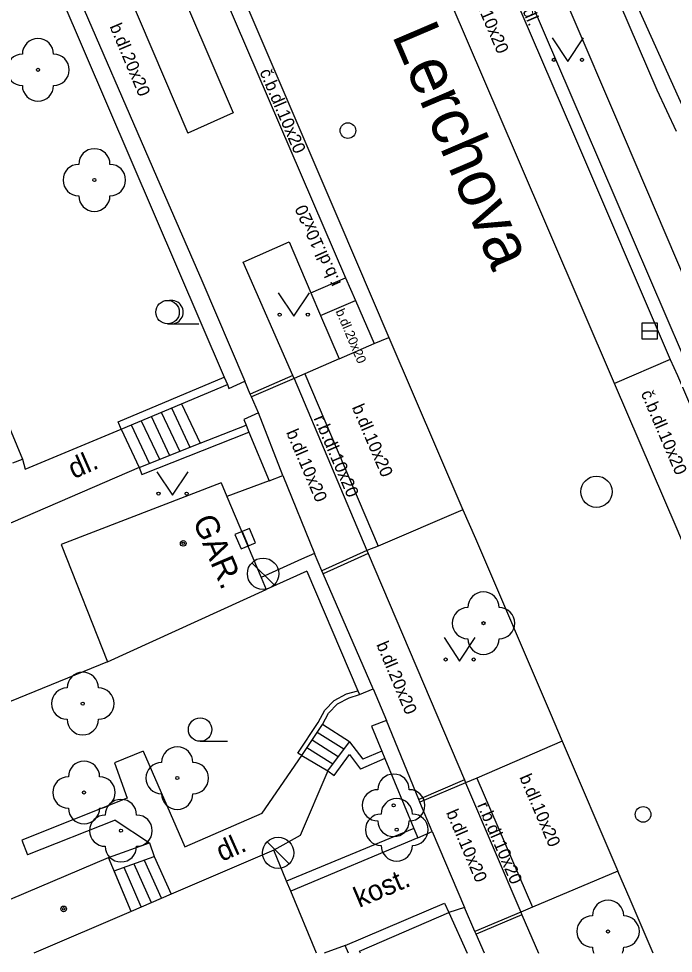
# Model space of a CAD drawing. Extents: x -600391 to -599491, y -1160176 to -1159402.
# Drawn here: x -599902.02 to -599881.11, y -1160176.08 to -1160146.21 of the extents above; entities that cross this region are included whole.
import ezdxf

# ---------------------------------------------------------------- set-up
doc = ezdxf.new("R2010")
doc.units = 0
for name, color, linetype in [('Level 10', 7, 'Continuous'), ('Level 11', 7, 'Continuous'), ('Level 22', 7, 'Continuous'), ('Level 27', 7, 'Continuous'), ('Level 28', 7, 'Continuous'), ('Level 36', 7, 'Continuous'), ('Level 39', 7, 'Continuous'), ('Level 40', 7, 'Continuous'), ('Level 41', 7, 'Continuous'), ('Level 5', 7, 'Continuous'), ('Level 50', 7, 'Continuous'), ('Level 6', 7, 'Continuous'), ('Level 7', 7, 'Continuous'), ('Level 8', 7, 'Continuous')]:
    doc.layers.add(name, color=color, linetype=linetype)

msp = doc.modelspace()

# ---------------------------------------------------------------- linework, layer by layer
at = {"layer": 'Level 10'}
for points in [[(-599900.25, -1160112.71), (-599895.14, -1160124.63), (-599894.96, -1160125.07), (-599894.75, -1160125.54), (-599893.06, -1160129.49), (-599892.08, -1160131.73), (-599890.71, -1160134.94), (-599890.53, -1160135.39), (-599884.33, -1160149.82), (-599881.2, -1160157.1), (-599880.97, -1160157.62), (-599879.19, -1160161.76), (-599879.01, -1160162.2)], [(-599903.64, -1160125.12), (-599901.38, -1160130.37), (-599899.78, -1160134.07), (-599895.66, -1160143.63), (-599891.79, -1160152.66), (-599890.19, -1160156.4), (-599887.83, -1160161.91), (-599887.42, -1160162.82), (-599885.04, -1160168.39), (-599884.65, -1160169.3), (-599882.88, -1160173.45)], [(-599881.745, -1160176.079), (-599882.48, -1160174.36), (-599882.88, -1160173.45)]]:
    msp.add_lwpolyline(points, dxfattribs=at)
at = {"layer": 'Level 11'}
msp.add_line((-599891.59, -1160175.83), (-599892.253, -1160176.079), dxfattribs=at)
for points in [[(-599880.3, -1160164.15), (-599880.98, -1160162.53), (-599882.98, -1160157.87), (-599886.11, -1160150.57), (-599892.31, -1160136.14), (-599894.43, -1160131.2), (-599896.75, -1160125.82), (-599902.04, -1160113.48), (-599906.68, -1160102.7), (-599908.55, -1160098.32), (-599910.62, -1160093.45), (-599915.66, -1160081.71)], [(-599889.36, -1160134.37), (-599889.32, -1160134.46), (-599882.98, -1160149.28), (-599879.7, -1160156.97), (-599879.66, -1160157.06)], [(-599880.57, -1160157.46), (-599880.81, -1160156.93), (-599883.94, -1160149.65), (-599890.33, -1160134.78)], [(-599902.82, -1160135.35), (-599902.78, -1160135.44), (-599896.61, -1160149.87)], [(-599896.16, -1160143.84), (-599891.58, -1160154.5), (-599891.26, -1160155.22), (-599890.66, -1160156.59)], [(-599897.27, -1160144.3), (-599895.16, -1160149.22), (-599896.61, -1160149.87)], [(-599894.85, -1160153.99), (-599893.38, -1160153.34), (-599892.68, -1160154.97), (-599892.37, -1160155.7), (-599891.78, -1160157.08)], [(-599893.22, -1160157.71), (-599893.26, -1160157.62), (-599894.85, -1160153.99)], [(-599892.68, -1160154.97), (-599891.58, -1160154.5)], [(-599892.37, -1160155.7), (-599891.26, -1160155.22)], [(-599891.78, -1160157.08), (-599890.66, -1160156.59), (-599890.19, -1160156.4)], [(-599891.78, -1160157.08), (-599892.88, -1160157.56)], [(-599881.2, -1160157.1), (-599882.98, -1160157.87)], [(-599893.26, -1160157.62), (-599894.62, -1160158.21)], [(-599892.88, -1160157.56), (-599893.22, -1160157.71)], [(-599892.88, -1160157.56), (-599890.53, -1160163.07)], [(-599893.22, -1160157.71), (-599894.58, -1160158.3)], [(-599893.22, -1160157.71), (-599890.89, -1160163.21)], [(-599896.82, -1160158.52), (-599896.22, -1160159.78)], [(-599897.46, -1160158.79), (-599896.87, -1160160.04)], [(-599897.14, -1160158.65), (-599896.55, -1160159.91)], [(-599898.42, -1160159.19), (-599897.85, -1160160.42)], [(-599898.1, -1160159.06), (-599897.52, -1160160.29)], [(-599897.78, -1160158.92), (-599897.2, -1160160.17)], [(-599901.81, -1160160.61), (-599898.74, -1160159.33)], [(-599898.74, -1160159.33), (-599898.17, -1160160.55)], [(-599901.9, -1160160.29), (-599901.81, -1160160.61)], [(-599898.17, -1160160.55), (-599902.6, -1160162.47)], [(-599894.01, -1160160.98), (-599895.37, -1160161.48)], [(-599887.83, -1160161.91), (-599890.53, -1160163.07)], [(-599890.53, -1160163.07), (-599890.89, -1160163.21)], [(-599890.89, -1160163.21), (-599892.33, -1160163.86)], [(-599890.85, -1160163.3), (-599892.29, -1160163.95)], [(-599890.89, -1160163.21), (-599890.85, -1160163.3), (-599887.78, -1160170.54), (-599887.74, -1160170.63)], [(-599891.63, -1160169.56), (-599892.48, -1160169.02)], [(-599891.45, -1160169.32), (-599892.31, -1160168.77)], [(-599891.81, -1160169.8), (-599892.64, -1160169.27)], [(-599884.65, -1160169.3), (-599887.38, -1160170.48), (-599887.74, -1160170.63)], [(-599898.04, -1160169.62), (-599898.96, -1160169.99)], [(-599898.04, -1160169.62), (-599896.71, -1160172.68)], [(-599891.98, -1160170.04), (-599892.81, -1160169.51)], [(-599894.24, -1160171.6), (-599892.97, -1160169.76)], [(-599892.97, -1160169.76), (-599892.14, -1160170.25)], [(-599898.96, -1160169.99), (-599898.55, -1160171.12)], [(-599892.14, -1160170.25), (-599893.03, -1160172.31)], [(-599887.78, -1160170.54), (-599889.23, -1160171.16)], [(-599887.38, -1160170.48), (-599885.6, -1160174.6)], [(-599887.74, -1160170.63), (-599889.2, -1160171.25)], [(-599887.74, -1160170.63), (-599885.98, -1160174.76)], [(-599898.55, -1160171.12), (-599901.92, -1160172.46)], [(-599896.71, -1160172.68), (-599894.24, -1160171.6)], [(-599898.94, -1160171.82), (-599901.73, -1160172.93)], [(-599898.94, -1160171.82), (-599897.84, -1160172.55)], [(-599893.03, -1160172.31), (-599893.87, -1160172.78)], [(-599901.92, -1160172.46), (-599901.73, -1160172.93)], [(-599898.34, -1160173.22), (-599897.79, -1160174.45)], [(-599898.01, -1160173.1), (-599897.47, -1160174.31)], [(-599897.69, -1160172.98), (-599897.15, -1160174.19)], [(-599898.66, -1160173.33), (-599898.11, -1160174.58)], [(-599882.88, -1160173.45), (-599885.6, -1160174.6), (-599885.98, -1160174.76)], [(-599885.98, -1160174.76), (-599887.44, -1160175.38)], [(-599885.94, -1160174.85), (-599887.4, -1160175.47)], [(-599885.98, -1160174.76), (-599885.94, -1160174.85), (-599885.415, -1160176.079)]]:
    msp.add_lwpolyline(points, dxfattribs=at)
at = {"layer": 'Level 22'}
for centre in [(-599901.4, -1160147.85), (-599899.6, -1160151.37), (-599887.17, -1160165.53), (-599899.97, -1160168.1), (-599896.95, -1160170.48), (-599899.93, -1160170.94), (-599890.04, -1160171.35), (-599898.75, -1160172.16), (-599889.94, -1160172.13), (-599883.19, -1160175.38)]:
    msp.add_circle(centre, 0.05, dxfattribs=at)
for centre, start, end in [((-599901.4, -1160147.35), 0, 180), ((-599901.9, -1160147.85), 90, 270), ((-599900.9, -1160147.85), 270, 90), ((-599901.4, -1160148.35), 180, 0), ((-599899.6, -1160150.87), 0, 180), ((-599900.1, -1160151.37), 90, 270), ((-599899.1, -1160151.37), 270, 90), ((-599899.6, -1160151.87), 180, 0), ((-599887.17, -1160165.03), 0, 180), ((-599887.67, -1160165.53), 90, 270), ((-599886.67, -1160165.53), 270, 90), ((-599887.17, -1160166.03), 180, 0), ((-599899.97, -1160167.6), 0, 180), ((-599900.47, -1160168.1), 90, 270), ((-599899.47, -1160168.1), 270, 90), ((-599899.97, -1160168.6), 180, 0), ((-599896.95, -1160169.98), 0, 180), ((-599899.93, -1160170.44), 0, 180), ((-599897.45, -1160170.48), 90, 270), ((-599896.45, -1160170.48), 270, 90), ((-599900.43, -1160170.94), 90, 270), ((-599899.43, -1160170.94), 270, 90), ((-599890.04, -1160170.85), 0, 180), ((-599896.95, -1160170.98), 180, 0), ((-599890.54, -1160171.35), 90, 270), ((-599889.94, -1160171.63), 0, 180), ((-599889.54, -1160171.35), 270, 90), ((-599899.93, -1160171.44), 180, 0), ((-599898.75, -1160171.66), 0, 180), ((-599899.25, -1160172.16), 90, 270), ((-599898.25, -1160172.16), 270, 90), ((-599890.44, -1160172.13), 90, 270), ((-599889.44, -1160172.13), 270, 90), ((-599890.04, -1160171.85), 180, 0), ((-599889.94, -1160172.63), 180, 0), ((-599898.75, -1160172.66), 180, 0), ((-599883.19, -1160174.88), 0, 180), ((-599883.69, -1160175.38), 90, 270), ((-599882.69, -1160175.38), 270, 90), ((-599883.19, -1160175.88), 180, 203.4042), ((-599883.19, -1160175.88), 336.5958, 0)]:
    msp.add_arc(centre, 0.5, start, end, dxfattribs=at)
at = {"layer": 'Level 27'}
for p, q in [((-599882.11, -1160156.19), (-599881.61, -1160156.19)), ((-599894.878, -1160162.6), (-599894.682, -1160163.06)), ((-599893.857, -1160164.304), (-599894.564, -1160163.597)), ((-599893.377, -1160173.224), (-599894.084, -1160172.517))]:
    msp.add_line(p, q, dxfattribs=at)
for points in [[(-599882.11, -1160156.44), (-599881.61, -1160156.44), (-599881.61, -1160155.94), (-599882.11, -1160155.94)], [(-599895.108, -1160162.698), (-599894.912, -1160163.158), (-599894.452, -1160162.962), (-599894.648, -1160162.502)]]:
    msp.add_lwpolyline(points, close=True, dxfattribs=at)
for centre in [(-599883.56, -1160161.33), (-599894.21, -1160163.95), (-599893.73, -1160172.87)]:
    msp.add_circle(centre, 0.5, dxfattribs=at)
at = {"layer": 'Level 28'}
for centre in [(-599891.5, -1160149.79), (-599882.07, -1160171.64)]:
    msp.add_circle(centre, 0.25, dxfattribs=at)
at = {"layer": 'Level 36'}
for p, q in [((-599897.26, -1160155.965), (-599896.26, -1160155.965)), ((-599896.22, -1160169.305), (-599895.345, -1160169.305))]:
    msp.add_line(p, q, dxfattribs=at)
for points in [[(-599884.97, -1160146.83), (-599884.47, -1160147.58), (-599883.97, -1160146.83)], [(-599893.73, -1160154.97), (-599893.23, -1160155.72), (-599892.73, -1160154.97)], [(-599897.6, -1160160.69), (-599897.1, -1160161.44), (-599896.6, -1160160.69)], [(-599888.43, -1160165.99), (-599887.93, -1160166.74), (-599887.43, -1160165.99)]]:
    msp.add_lwpolyline(points, dxfattribs=at)
for centre, radius in [((-599884.92, -1160147.53), 0.05), ((-599884.021, -1160147.53), 0.05), ((-599897.26, -1160155.59), 0.375), ((-599893.68, -1160155.67), 0.05), ((-599892.781, -1160155.67), 0.05), ((-599897.55, -1160161.39), 0.05), ((-599896.651, -1160161.39), 0.05), ((-599888.38, -1160166.69), 0.05), ((-599887.481, -1160166.69), 0.05), ((-599896.22, -1160168.93), 0.375)]:
    msp.add_circle(centre, radius, dxfattribs=at)
msp.add_arc((-599897.135, -1160155.59), 0.375, 260.4059, 99.5941, dxfattribs=at)
at = {"layer": 'Level 39'}
for centre, radius in [((-599896.76, -1160162.98), 0.09), ((-599896.76, -1160162.98), 0.0398), ((-599900.58, -1160174.66), 0.09), ((-599900.58, -1160174.66), 0.0398)]:
    msp.add_circle(centre, radius, dxfattribs=at)
at = {"layer": 'Level 5'}
for points in [[(-599895.55, -1160161.04), (-599900.66, -1160163.02)], [(-599895.55, -1160161.04), (-599895.37, -1160161.48), (-599894.27, -1160164.07), (-599894.11, -1160164.45)], [(-599900.66, -1160163.02), (-599899.18, -1160166.76)], [(-599899.18, -1160166.76), (-599894.11, -1160164.45)], [(-599893.87, -1160172.78), (-599897.15, -1160174.19), (-599898.42, -1160174.74), (-599901.538, -1160176.079)], [(-599892.503, -1160176.079), (-599893.32, -1160174.09), (-599893.46, -1160173.77), (-599893.87, -1160172.78)], [(-599902.72, -1160174.53), (-599899.15, -1160173.02)], [(-599898.42, -1160174.74), (-599899.15, -1160173.02)], [(-599898.42, -1160174.74), (-599898.97, -1160173.44)]]:
    msp.add_lwpolyline(points, dxfattribs=at)
at = {"layer": 'Level 6'}
msp.add_line((-599892.503, -1160176.079), (-599893.32, -1160174.09), dxfattribs=at)
at = {"layer": 'Level 7'}
for points in [[(-599904.36, -1160135.72), (-599904.25, -1160135.96), (-599904.21, -1160136.06), (-599900.17, -1160145.36), (-599897.86, -1160150.69), (-599897.61, -1160151.26), (-599896.17, -1160154.58), (-599894.79, -1160157.8)], [(-599886.79, -1160136.46), (-599883.12, -1160145.01), (-599881.63, -1160148.49), (-599881.01, -1160149.81)], [(-599880.53, -1160149.62), (-599882.7, -1160144.81)], [(-599900.67, -1160145.51), (-599895.45, -1160157.67), (-599895.35, -1160157.9), (-599895.3, -1160158.03)], [(-599903.77, -1160155.79), (-599901.9, -1160160.29)], [(-599898.84, -1160159.1), (-599895.45, -1160157.67)], [(-599898.74, -1160159.33), (-599896.82, -1160158.52), (-599895.35, -1160157.9)], [(-599895.3, -1160158.03), (-599894.79, -1160157.8)], [(-599894.36, -1160158.81), (-599894.82, -1160159.02)], [(-599893.58, -1160160.81), (-599894.36, -1160158.81)], [(-599898.74, -1160159.33), (-599898.84, -1160159.1)], [(-599898.17, -1160160.55), (-599896.22, -1160159.78), (-599894.75, -1160159.2)], [(-599894.82, -1160159.02), (-599894.75, -1160159.2), (-599894.66, -1160159.43), (-599894.01, -1160160.98)], [(-599898.08, -1160160.78), (-599894.66, -1160159.43)], [(-599902.2, -1160160.41), (-599901.9, -1160160.29)], [(-599898.17, -1160160.55), (-599898.08, -1160160.78)], [(-599894.01, -1160160.98), (-599893.58, -1160160.81)], [(-599892.57, -1160163.3), (-599892.98, -1160163.48)], [(-599890.69, -1160167.63), (-599892.29, -1160163.95), (-599892.33, -1160163.86), (-599892.57, -1160163.3)], [(-599892.98, -1160163.48), (-599894.27, -1160164.07)], [(-599892.81, -1160163.87), (-599894.11, -1160164.45)], [(-599892.81, -1160163.87), (-599891.18, -1160167.69)], [(-599899.18, -1160166.76), (-599908.82, -1160170.7)], [(-599892.45, -1160168.7), (-599892.24, -1160168.31), (-599891.94, -1160168), (-599891.55, -1160167.79), (-599891.18, -1160167.69)], [(-599892.31, -1160168.77), (-599892.12, -1160168.4), (-599891.83, -1160168.11), (-599891.46, -1160167.92), (-599891.13, -1160167.81)], [(-599891.18, -1160167.69), (-599891.13, -1160167.81)], [(-599891.13, -1160167.81), (-599890.69, -1160167.63)], [(-599893.1, -1160169.68), (-599892.45, -1160168.7)], [(-599890.27, -1160168.64), (-599890.75, -1160168.82)], [(-599888.81, -1160172.19), (-599889.2, -1160171.25), (-599889.23, -1160171.16), (-599890.27, -1160168.64)], [(-599892.97, -1160169.76), (-599892.31, -1160168.77)], [(-599890.75, -1160168.82), (-599890.42, -1160169.62), (-599890.32, -1160169.85), (-599889.39, -1160172.09), (-599889.27, -1160172.39)], [(-599892.14, -1160170.25), (-599891.45, -1160169.32)], [(-599891.45, -1160169.32), (-599891.02, -1160169.88)], [(-599890.42, -1160169.62), (-599891.02, -1160169.88)], [(-599892.97, -1160169.76), (-599893.1, -1160169.68)], [(-599891.94, -1160170.4), (-599891.45, -1160169.73)], [(-599891.45, -1160169.73), (-599891.1, -1160170.19)], [(-599890.32, -1160169.85), (-599891.1, -1160170.19)], [(-599892.14, -1160170.25), (-599891.94, -1160170.4)], [(-599889.39, -1160172.09), (-599893.46, -1160173.77)], [(-599889.27, -1160172.39), (-599888.81, -1160172.19)], [(-599899.15, -1160173.02), (-599897.84, -1160172.55)], [(-599897.84, -1160172.55), (-599897.69, -1160172.98)], [(-599889.27, -1160172.39), (-599893.32, -1160174.09)], [(-599898.97, -1160173.44), (-599897.69, -1160172.98)], [(-599891.485, -1160176.079), (-599891.59, -1160175.83), (-599888.41, -1160174.48)], [(-599888.41, -1160174.48), (-599888.28, -1160174.77), (-599887.691, -1160176.079)], [(-599887.78, -1160174.61), (-599888.28, -1160174.77)], [(-599887.132, -1160176.079), (-599887.4, -1160175.47), (-599887.44, -1160175.38), (-599887.78, -1160174.61)], [(-599891.101, -1160176.079), (-599891.13, -1160176.01), (-599888.28, -1160174.77)]]:
    msp.add_lwpolyline(points, dxfattribs=at)
at = {"layer": 'Level 8'}
for points in [[(-599894.36, -1160158.81), (-599894.58, -1160158.3), (-599894.62, -1160158.21), (-599894.79, -1160157.8)], [(-599893.58, -1160160.81), (-599892.57, -1160163.3)], [(-599890.69, -1160167.63), (-599890.27, -1160168.64)], [(-599888.81, -1160172.19), (-599887.78, -1160174.61)]]:
    msp.add_lwpolyline(points, dxfattribs=at)

# ---------------------------------------------------------------- texts
at = {"layer": 'Level 40'}
for s, height, rotation, p in [('b.dl.10x20', 0.4, 293.1381, (-599887.68, -1160145.1)), ('zatr.dl.', 0.4, 293.3292, (-599886.34, -1160145.01)), ('b.dl.20x20', 0.4, 292.7805, (-599899.12, -1160146.46)), ('č.b.dl.10x20', 0.4, 293.1381, (-599894.33, -1160147.91)), ('r.b.dl.10x20', 0.39992, 114, (-599891.71, -1160154.67)), ('b.dl.20x20', 0.3, 293.0615, (-599891.9, -1160155.56)), ('č.b.dl.10x20', 0.4, 293.1381, (-599882.15, -1160158.18)), ('b.dl.10x20', 0.4, 293.1381, (-599891.38, -1160158.63)), ('r.b.dl.10x20', 0.39995, 293.1661, (-599892.6, -1160158.98)), ('b.dl.10x20', 0.4, 293.1381, (-599893.48, -1160159.43)), ('dl.', 0.65, 23.6029, (-599900.26, -1160160.93)), ('dl.', 0.65, 23.6029, (-599900.26, -1160160.93)), ('b.dl.20x20', 0.4, 292.7805, (-599890.6, -1160166.21)), ('b.dl.10x20', 0.4, 293.1381, (-599886.03, -1160170.45)), ('r.b.dl.10x20', 0.39995, 293.1661, (-599887.38, -1160171.34)), ('b.dl.10x20', 0.4, 293.1381, (-599888.37, -1160171.58)), ('dl.', 0.65, 24, (-599895.53, -1160173.16)), ('kost.', 0.65, 23.0569, (-599891.14, -1160174.63))]:
    msp.add_text(s, height=height, rotation=rotation, dxfattribs=at).set_placement(p)
at = {"layer": 'Level 41'}
msp.add_text('GAR.', height=0.75, rotation=293.042, dxfattribs=at).set_placement((-599896.47, -1160162.25))
at = {"layer": 'Level 50'}
msp.add_text('Lerchova', height=1.5, rotation=293.155, dxfattribs=at).set_placement((-599890.107, -1160146.739))

doc.saveas('drawing.dxf')
